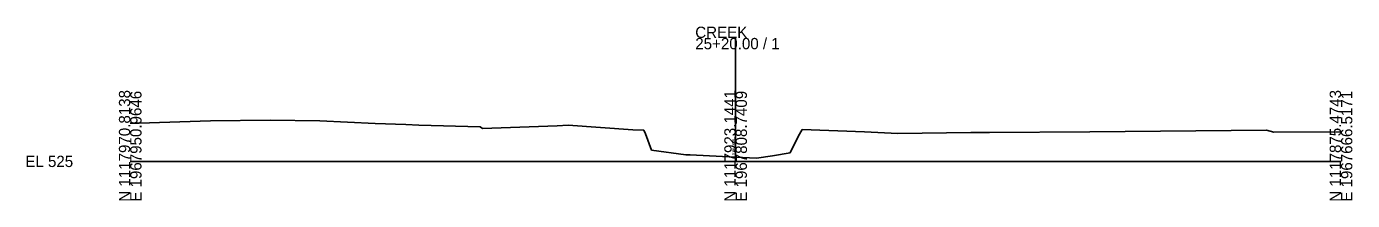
# Model space of a CAD drawing. Extents: x 9974 to 10303, y 9990 to 19550.
# Drawn here: x 9974.3 to 10302.8, y 14990.3 to 15033.4 of the extents above; entities that cross this region are included whole.
import ezdxf

# ---------------------------------------------------------------- set-up
doc = ezdxf.new("R2010")
doc.units = 0
for name, color, linetype in [('Level 10', 7, 'Continuous'), ('Level 60', 7, 'Continuous'), ('Level 63', 7, 'Continuous')]:
    doc.layers.add(name, color=color, linetype=linetype)

msp = doc.modelspace()

# ---------------------------------------------------------------- linework, layer by layer
at = {"layer": 'Level 60'}
for p, q in [((10000, 15009.51), (10002.23, 15009.44)), ((10002.23, 15009.44), (10019.89, 15010.01)), ((10019.89, 15010.01), (10034.71, 15010.2)), ((10034.71, 15010.2), (10046.97, 15010.07)), ((10046.97, 15010.07), (10060.65, 15009.43)), ((10060.65, 15009.43), (10068.28, 15009.15)), ((10068.28, 15009.15), (10071.53, 15008.98)), ((10071.53, 15008.98), (10086.67, 15008.59)), ((10086.67, 15008.59), (10087.27, 15008.18)), ((10087.27, 15008.18), (10105.75, 15008.81)), ((10105.75, 15008.81), (10108.52, 15008.99)), ((10108.52, 15008.99), (10124.51, 15007.81)), ((10124.51, 15007.81), (10127.23, 15007.72)), ((10127.23, 15007.72), (10127.65, 15006.8)), ((10165.5, 15006.18), (10166.47, 15007.9)), ((10166.47, 15007.9), (10181.97, 15007.31)), ((10237.8, 15007.3), (10281.5, 15007.71)), ((10281.5, 15007.71), (10283.36, 15007.27)), ((10127.65, 15006.8), (10129.15, 15002.74)), ((10163.5, 15002.15), (10165.5, 15006.18)), ((10181.97, 15007.31), (10190.23, 15006.91)), ((10190.23, 15006.91), (10208.25, 15007.17)), ((10208.25, 15007.17), (10212.88, 15007.19)), ((10212.88, 15007.19), (10237.8, 15007.3)), ((10283.36, 15007.27), (10300, 15007.32)), ((10129.15, 15002.74), (10137.63, 15001.62)), ((10137.63, 15001.62), (10138.76, 15001.61)), ((10138.76, 15001.61), (10150, 15001.06)), ((10150, 15001.06), (10155.19, 15000.8)), ((10155.19, 15000.8), (10159.12, 15001.37)), ((10159.12, 15001.37), (10163.5, 15002.15))]:
    msp.add_line(p, q, dxfattribs=at)
at = {"layer": 'Level 63'}
for p, q in [((10150, 15000), (10150, 15030.59)), ((10000, 15000), (10150, 15000)), ((10150, 15000), (10300, 15000))]:
    msp.add_line(p, q, dxfattribs=at)

# ---------------------------------------------------------------- texts
at = {"layer": 'Level 10'}
msp.add_text('526.059', height=0.8, rotation=90, dxfattribs=at).set_placement((10149.9, 15001.56))
at = {"layer": 'Level 63'}
for s, p in [('CREEK', (10140, 15030.59)), ('25+20.00 / 1', (10140, 15027.79)), ('EL 525', (9974, 14998.6))]:
    msp.add_text(s, height=2.8, dxfattribs=at).set_placement(p)
for s, p in [('N 1117970.8138', (10000, 14990)), ('E 1967950.9646', (10002.8, 14990)), ('N 1117923.1441', (10150, 14990)), ('E 1967808.7409', (10152.8, 14990)), ('N 1117875.4743', (10300, 14990)), ('E 1967666.5171', (10302.8, 14990))]:
    msp.add_text(s, height=2.8, rotation=90, dxfattribs=at).set_placement(p)

doc.saveas('drawing.dxf')
